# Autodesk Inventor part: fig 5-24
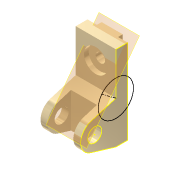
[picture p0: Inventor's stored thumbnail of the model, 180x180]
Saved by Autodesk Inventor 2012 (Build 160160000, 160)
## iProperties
Shininess: 65.0
Angle Display Precision: 2
Document Length Units: 11269
Document Angle Units: 11279
Document Time Units: 11290
Document Mass Units: 11283
Document Length Units Precision: 3
Document Angle Units Precision: 2
Compacted: False
Created: 2001-11
Part Number: fig 5-24
Document SubType Name: Modeling
Designer: Renu Muthoo
Density: 1 g/cm^3
Material: Default
Density: 0.0
Volumn: 0.0
Area: 0.0
PropertySet Name: Model Information
Control State: 0
Master: False
Checked Out: False
Author: Renu Muthoo
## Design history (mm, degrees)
node "Sketch1"
sketch "Sketch2"
  geometry: L1 (33.257, 104.664)-(33.257, -75.336); L2 (33.257, -75.336)-(8.257, -75.336); L3 (8.257, -75.336)-(-45.451, -59.045); L4 (-45.451, -1.628)-(8.257, 14.664); L5 (8.257, 14.664)-(8.257, 104.664); L6 (8.257, 104.664)-(33.257, 104.664); C1 r 15 at (-36.743, -30.336); A1 r 30 centre (-36.743, -30.336) between (-45.451, -1.628) and (-45.451, -59.045)
  constraints: 12 end point, 2 centre point, 2 equal length, 2 parallel, 2 point on circle, 2 tangent, 1 coincident, 1 perpendicular, 1 vertical
  dimensions: "d0" = 180 distance of L1.start L1.end; "d1" = 30 radius of A1; "d2" = 25 distance of L5.end L1.start; "d3" = 45 distance from line of L2 A1.centre; "d4" = 70 distance from line of L1 A1.centre; "d5" = 30 diameter of C1
extrude "Extrusion1" new body sketch "Sketch2" distance "d6" = 85; taper "d7" = 0 deg
workplane "Work Plane1"
sketch "Sketch3"
  geometry: L1 (15, 62.364)-(70, 62.364); L2 (70, 62.364)-(70, -52.386); L3 (70, -52.386)-(15, -52.386); L4 (15, -52.386)-(15, 62.364); L5 (0, -45)-(0, -28.708) reference
  constraints: 8 end point, 2 parallel, 1 horizontal, 1 perpendicular
  dimensions: "d8" = 55 distance of L1.start L1.end; "d9" = 15 distance between parallel lines of L5 L4
extrude "Extrusion2" cut sketch "Sketch3" distance "d10" = 50; taper "d11" = 0 deg
sketch "Sketch4"
  geometry: L1 (0, 25)-(85, 25) reference; L2 (0, 0)-(0, 25) reference; L3 (20, 25)-(65, 25); L4 (65, 25)-(65, 35); L5 (65, 35)-(20, 35); L6 (20, 35)-(20, 25)
  constraints: 8 end point, 2 parallel, 1 horizontal, 1 perpendicular, 1 point on line
  dimensions: "d12" = 45 distance of L4.end L5.end; "d13" = 10 distance of L3.end L4.end; "d14" = 20 distance between parallel lines of L2 L6
extrude "Extrusion3" join sketch "Sketch4" stored distance "d15" = 50; taper "d16" = 0 deg
sketch "Sketch5"
  geometry: L1 (85, 0)-(85, 90) reference; L2 (0, 90)-(85, 90) reference; 1 further point
  dimensions: "d17" = 42 distance from line of L2 point (42.5, 48); "d18" = 42.5 distance from line of L1 point (42.5, 48)
hole "Hole1" sketch "Sketch5" at (42.5, 48) diameter "d19" = 20; stored, may be unused: countersink angle "d23" = 82 deg, drill point angle "d25" = 118 deg; dims "d20" = 6, "d21" = 50, "d22" = 10, "d24" = 8
sketch "Sketch8"
  geometry: L1 (75.336, 33.257)-(75.336, 8.257) reference; L2 (-104.664, 33.257)-(75.336, 33.257) reference; L3 (-104.664, 8.257)-(-104.664, 33.257) reference; L4 (-14.664, 8.257)-(-104.664, 8.257) reference; L5 (1.628, -45.451)-(-14.664, 8.257) reference; L6 (75.336, 8.257)-(59.045, -45.451) reference; C1 r 15 at (30.336, -36.743) reference; C2 r 37.437 at (-14.664, 8.257); A1 r 30 centre (30.336, -36.743) between (1.628, -45.451) and (59.045, -45.451) reference
  constraints: 1 centre point, 1 coincident
sketch "Sketch9"
  geometry: L1 (75.336, 33.257)-(75.336, 8.257) reference; L2 (-14.664, 8.257)-(-104.664, 8.257) reference; L3 (1.628, -45.451)-(-14.664, 8.257) reference; L4 (75.336, 8.257)-(59.045, -45.451) reference; L5 (-14.664, 8.257)-(-37, -21.743); C1 r 15 at (30.336, -36.743) reference; A1 r 30 centre (30.336, -36.743) between (1.628, -45.451) and (59.045, -45.451) reference
  constraints: 2 end point
workplane "Work Plane11"
body "Solid1"
